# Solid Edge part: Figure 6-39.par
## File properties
Author: CADCIM
Template: Normal.par
Last saved by: Ashutosh-CADCIM
Revision: 7
Application: Solid Edge
Accuracy: 0.99
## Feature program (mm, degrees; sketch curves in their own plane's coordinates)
sketch for "unnamed Protrusion 1" plane through (0, 0, 0) normal (0, -1, 0) x-axis (1, 0, 0)
  circle centre (0, 0) radius 43.5332
extrude "unnamed Protrusion 1" add finite 19.05 symmetric
sketch for "ExtrudedProtrusion_2" plane through (0, -9.525, 0) normal (0, -1, 0) x-axis (1, 0, 0)
  circle centre (0, 0) radius 20.3532
extrude "ExtrudedProtrusion_2" add finite 15.875 along +normal
sketch for "unnamed Cutout 1" plane through (0, -9.525, 0) normal (0, -1, 0) x-axis (1, 0, 0)
  arc centre (0, 0) radius 12.0084 from (4.2834, 11.2184) to (-4.2834, 11.2184) cw
  line (-4.2834, 15.2603) -> (-4.2834, 11.2184)
  line (4.2834, 15.2603) -> (-4.2834, 15.2603)
  line (4.2834, 11.2184) -> (4.2834, 15.2603)
extrude "unnamed Cutout 1" cut through along +normal
sketch for "unnamed Cutout 2" plane through (0, -9.525, 0) normal (0, -1, 0) x-axis (1, 0, 0)
  circle centre (0, 33.0061) radius 4
extrude "unnamed Cutout 2" cut through along -normal
pattern "unnamed Pattern 1" of "unnamed Cutout 2"
pattern "unnamed Pattern 2"
fillet "Round_1" radius 2
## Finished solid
Body 1: solid body, 18 faces, 33 edges, 8 vertices.
  Faces by surface: cylinder 11, plane 6, torus 1
  Edges by curve: circle 23, line 10
Bounding box of the edges (mm; curved faces can reach further): 87.066 x 34.925 x 87.066, from (-43.5332, -25.4, -43.5332) to (43.5332, 9.525, 43.5332).
Cylindrical faces by radius (mm): R4 x8, R12.0084 x1, R20.3532 x1, R43.5332 x1
Toroidal faces (ring radius, tube radius in mm): R22.3532 r2 x1
Planar faces by outward normal: +x 1, +y 1, -x 1, -y 2, -z 1
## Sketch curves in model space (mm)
circle centre (0, -9.525, 33.0061) radius 4
line (4.2834, -9.525, 15.2603) -> (-4.2834, -9.525, 15.2603)
line (-4.2834, -9.525, 15.2603) -> (-4.2834, -9.525, 11.2184)
arc centre (0, -9.525, 0) radius 12.0084 from (4.2834, -9.525, 11.2184) through (-0.7167, -9.525, -11.987) to (-4.2834, -9.525, 11.2184)
line (4.2834, -9.525, 11.2184) -> (4.2834, -9.525, 15.2603)
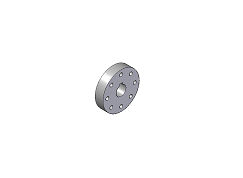
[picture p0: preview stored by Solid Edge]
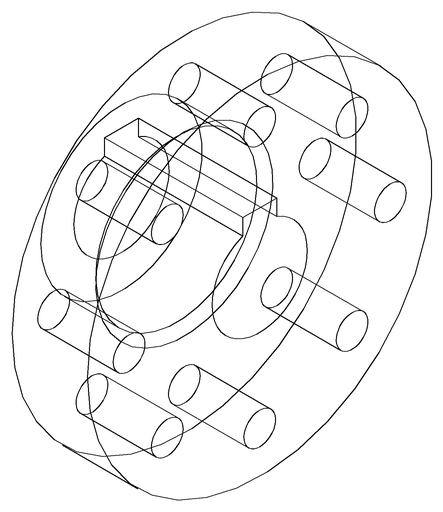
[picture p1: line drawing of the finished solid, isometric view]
